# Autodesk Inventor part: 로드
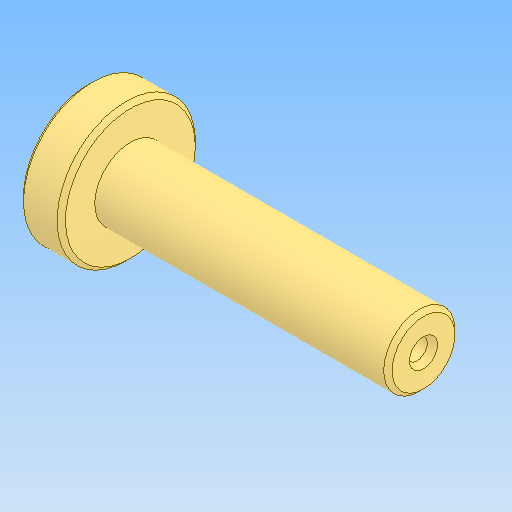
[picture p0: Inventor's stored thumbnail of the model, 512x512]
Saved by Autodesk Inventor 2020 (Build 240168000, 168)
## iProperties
Created: 2024-09
Part Number: 로드
Material: 강철, 탄소
Document SubType Name: Modeling
Designer: oem
Density: 7.85 g/cm^3
Appearance: 기본값
Author: jhkim
Sending System: Autodesk Inventor 2025
Preprocessor: ST-DEVELOPER v20
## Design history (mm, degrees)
feature "솔리드1"
node "솔리드2"
